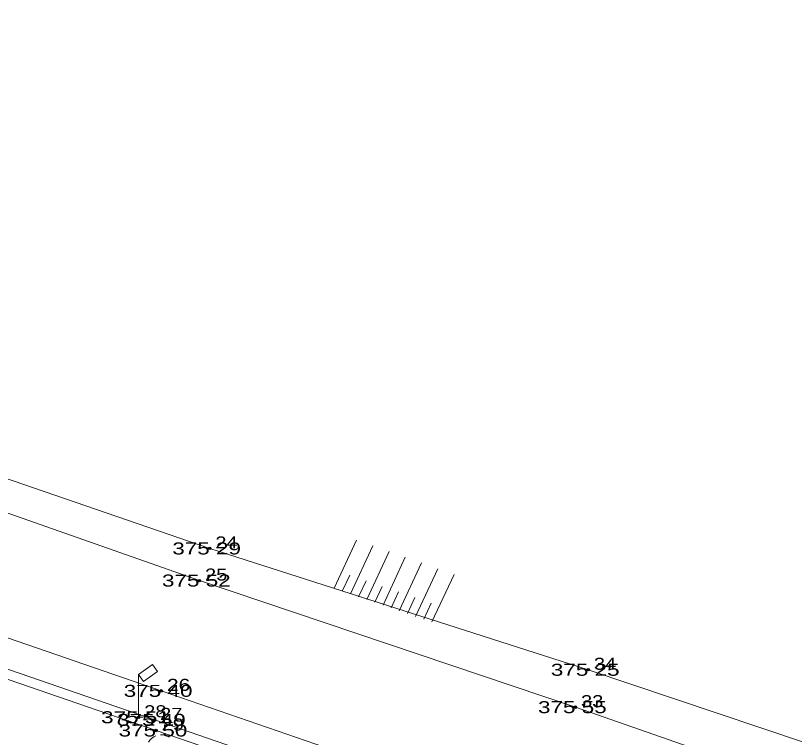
# Model space of a CAD drawing. Extents: x -789669 to -789458, y -977587 to -977420.
# Drawn here: x -789574.69 to -789529.27, y -977462.39 to -977420.32 of the extents above; entities that cross this region are included whole.
import ezdxf
from ezdxf.enums import TextEntityAlignment as Align

# ---------------------------------------------------------------- set-up
doc = ezdxf.new("R2010")
doc.units = 0
doc.header["$LTSCALE"] = 0.28
doc.header["$PDMODE"] = 32
doc.header["$PDSIZE"] = 0.14
for name, color, linetype, lineweight in [('1', 7, 'Continuous', 13), ('2', 7, 'Continuous', 13), ('3', 7, 'Continuous', 13), ('33', 7, 'Continuous', 13), ('4', 7, 'Continuous', 13)]:
    doc.layers.add(name, color=color, linetype=linetype, lineweight=lineweight)
for name, color, linetype in [('57', 7, 'Continuous'), ('58', 7, 'Continuous'), ('59', 7, 'Continuous')]:
    doc.layers.add(name, color=color, linetype=linetype)

msp = doc.modelspace()

# ---------------------------------------------------------------- linework, layer by layer
at = {"layer": '1'}
for points in [[(-789652.33, -977422.61), (-789627.98, -977430.97), (-789609.02, -977437.54), (-789583.63, -977446.35), (-789563.97, -977453.25), (-789542.04, -977460.63), (-789524.21, -977466.84), (-789507.23, -977472.64), (-789487.17, -977479.36)], [(-789509.64, -977479.12), (-789526.32, -977473.4), (-789544.78, -977467.07), (-789566.2, -977459.68), (-789586.28, -977452.77), (-789604.78, -977446.41), (-789630.61, -977437.53), (-789654.9, -977429.37)], [(-789604.26, -977448.38), (-789586.79, -977454.41), (-789566.59, -977461.37), (-789545.35, -977468.71), (-789526.33, -977475.15), (-789510.21, -977480.66), (-789489.34, -977487.73), (-789463.94, -977496.44)]]:
    msp.add_lwpolyline(points, dxfattribs=at)
at = {"layer": '2'}
for p, q in [((-789554.807, -977450.889), (-789556.118, -977453.702)), ((-789555.167, -977454.029), (-789553.86, -977451.224)), ((-789554.216, -977454.356), (-789552.912, -977451.558)), ((-789553.265, -977454.683), (-789551.965, -977451.893)), ((-789552.315, -977455.01), (-789551.018, -977452.227)), ((-789551.364, -977455.337), (-789550.07, -977452.562)), ((-789555.643, -977453.866), (-789555.206, -977452.929)), ((-789554.692, -977454.193), (-789554.256, -977453.259)), ((-789550.413, -977455.664), (-789549.123, -977452.897)), ((-789553.741, -977454.52), (-789553.307, -977453.588)), ((-789552.79, -977454.847), (-789552.357, -977453.917)), ((-789551.839, -977455.174), (-789551.407, -977454.247)), ((-789550.888, -977455.501), (-789550.458, -977454.576))]:
    msp.add_line(p, q, dxfattribs=at)
msp.add_lwpolyline([(-789651.99, -977420.32), (-789627.42, -977429.7), (-789608.58, -977435.72), (-789582.71, -977444.73), (-789563.37, -977451.38), (-789541.29, -977458.45), (-789523.64, -977464.38), (-789506.63, -977471.11), (-789487.17, -977479.36)], dxfattribs=at)
at = {"layer": '3'}
msp.add_lwpolyline([(-789601.84, -977457.06), (-789598.55, -977450.95), (-789566.5, -977461.99), (-789545.47, -977469.2), (-789526.54, -977475.63), (-789520.95, -977477.5)], dxfattribs=at)
at = {"layer": '33'}
for p, q in [((-789567.52, -977458.72), (-789567.52, -977461.22)), ((-789567.77, -977461.22), (-789567.27, -977461.22))]:
    msp.add_line(p, q, dxfattribs=at)
msp.add_lwpolyline([(-789567.52, -977458.72), (-789566.7, -977458.147), (-789566.414, -977458.557), (-789567.234, -977459.13)], close=True, dxfattribs=at)
at = {"layer": '4'}
for start, end in [(111.04924, 149.34666), (57.94289, 92.85253)]:
    msp.add_arc((-789566.1939, -977463.1194), 0.875, start, end, dxfattribs=at)
at = {"layer": '57'}
for p in [(-789563.37, -977451.38), (-789563.97, -977453.25), (-789541.29, -977458.45), (-789566.2, -977459.68), (-789542.04, -977460.63), (-789567.52, -977461.22), (-789566.59, -977461.37), (-789566.5, -977461.99)]:
    msp.add_point(p, dxfattribs=at)

# ---------------------------------------------------------------- texts
at = {"layer": '58'}
for s, width, p in [(' 24', 1.25, (-789563.37, -977451.38)), (' 25', 1.25, (-789563.97, -977453.25)), (' 34', 1.25, (-789541.29, -977458.45)), (' 26', 1.3, (-789566.2, -977459.68)), (' 33', 1.25, (-789542.04, -977460.63)), (' 28', 1.25, (-789567.52, -977461.22)), (' 27', 1.25, (-789566.59, -977461.37)), (' 29', 1.25, (-789566.5, -977461.99))]:
    msp.add_text(s, height=0.7, dxfattribs=dict(at, width=width)).set_placement(p)
at = {"layer": '59', "width": 1.4}
for s, p in [('375 29 ', (-789563.37, -977451.73)), ('375 52 ', (-789563.97, -977453.6)), ('375 25 ', (-789541.29, -977458.8)), ('375 40 ', (-789566.2, -977460.03)), ('375 55 ', (-789542.04, -977460.98)), ('375 51 ', (-789567.52, -977461.57)), ('375 49 ', (-789566.59, -977461.72)), ('375 50 ', (-789566.5, -977462.34))]:
    msp.add_text(s, height=0.7, dxfattribs=at).set_placement(p, align=Align.CENTER)

doc.saveas('drawing.dxf')
